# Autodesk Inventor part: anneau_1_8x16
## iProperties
Created: 2011-01
Part Number: anneau_1_8x16
Document SubType Name: Modeling
Designer: eric
Density: 1 g/cm^3
Mass: 0.12791 g
Surface Area: 2.84245 cm^2
Volume: 0.12791 cm^3
Author: eric
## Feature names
1. Base1
